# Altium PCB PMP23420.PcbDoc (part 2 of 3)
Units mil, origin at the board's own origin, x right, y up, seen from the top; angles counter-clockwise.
Board outline 5200 x 3400 mil, 6 copper layers (Top Layer, Midlayer 1, Midlayer 2, Midlayer 3, Midlayer 4, Bottom Layer), stack 61.536 mil thick; 227 components, 56 nets, 480 pads, 964 vias.
Unrouted connection lines stored in the file: 22.
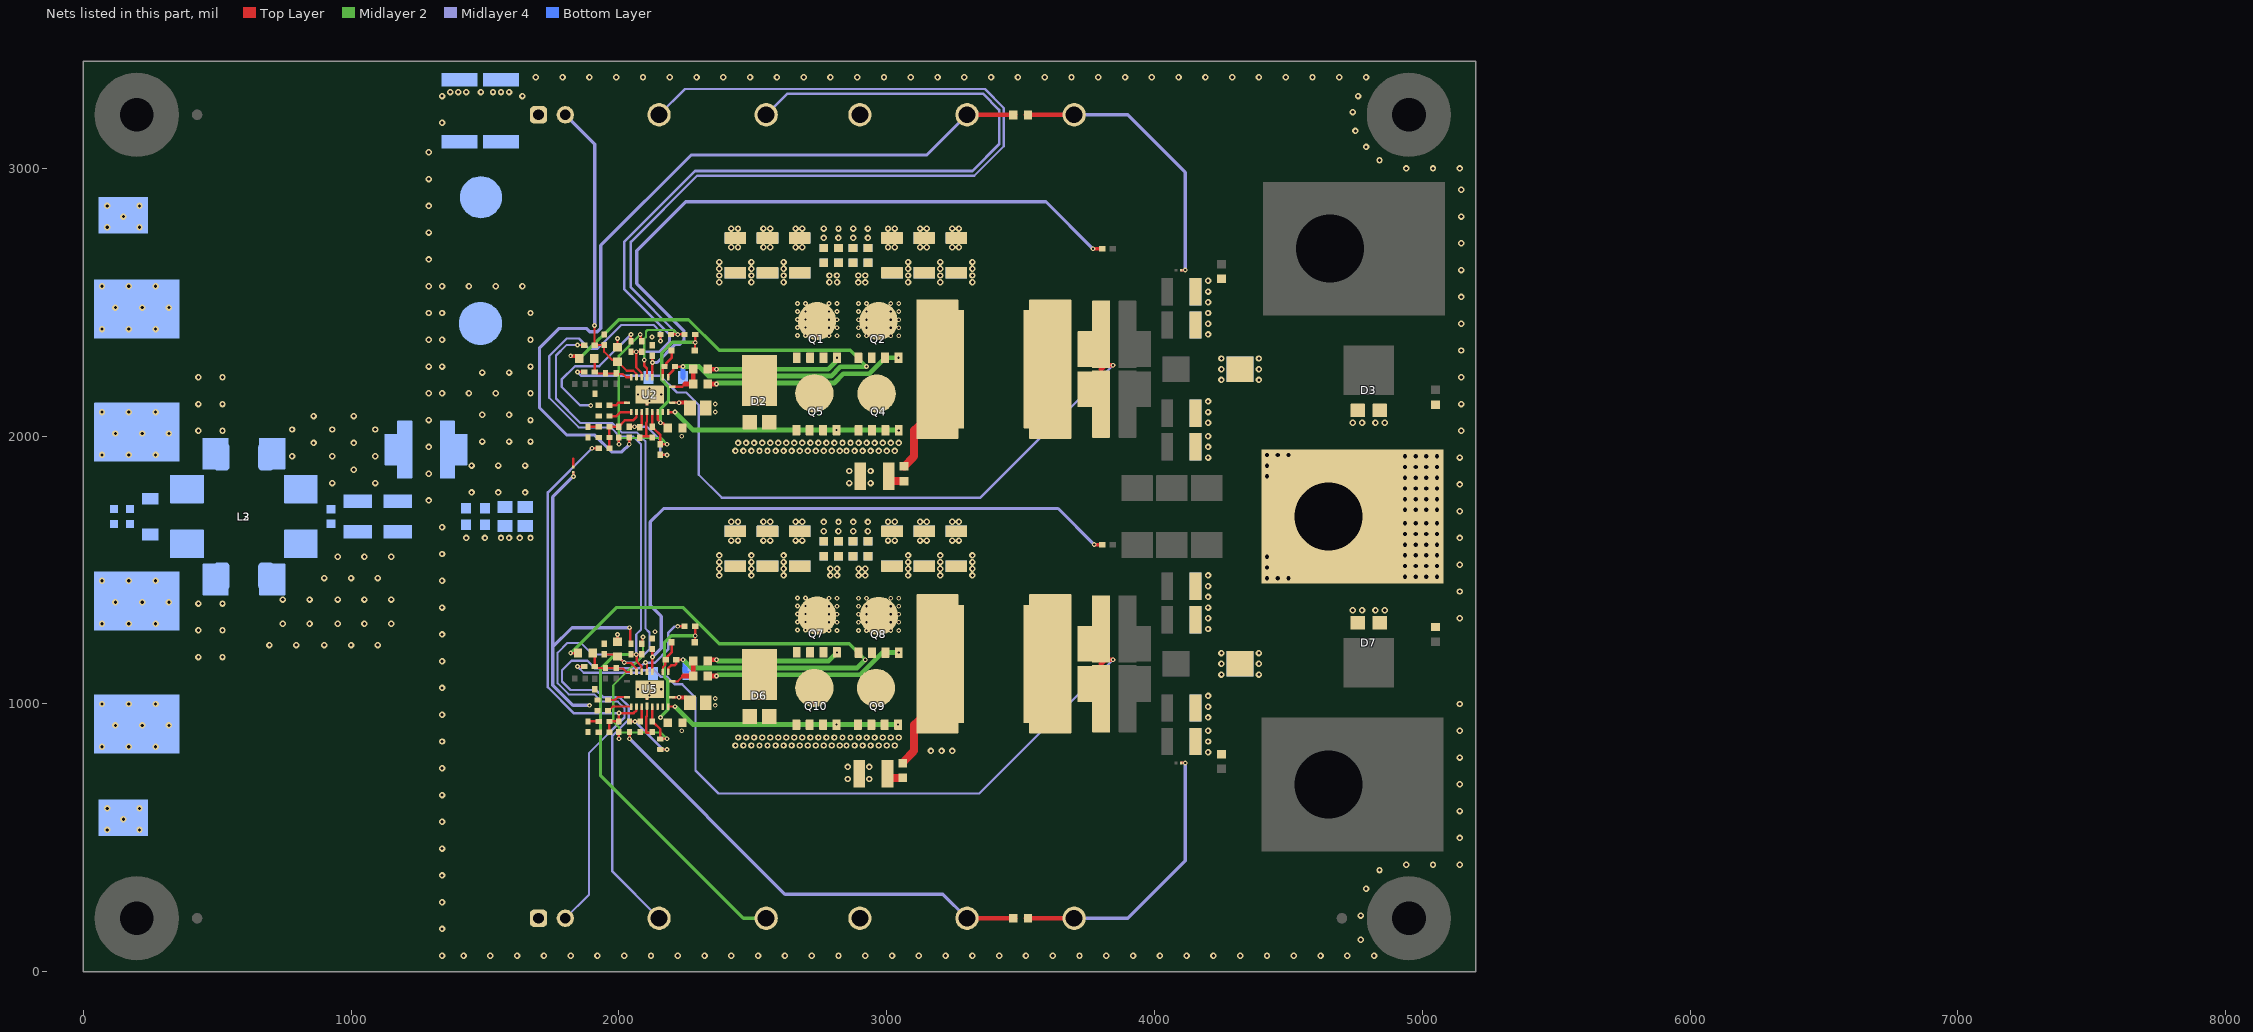
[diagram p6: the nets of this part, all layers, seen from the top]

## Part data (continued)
C51 C93: library part CMP-0006311-2, "CAP, CERM, 22 pF, 50 V, +/- 5%, C0G/NP0, AEC-Q200 Grade 1, 0402", Cap_Case=0402, Manufacturer=TDK, Supplier Part Number 1=445-12130-1-ND, TempCo=C0G/NP0, Tolerance_%=5%, Value1=Unknown, Value2=50V, ValueDisplayed=22pF
C52: library part CMP-0006353-2, "CAP, CERM, 0.022 uF, 25 V, +/- 10%, X7R, AEC-Q200 Grade 1, 0402", Cap_Case=0402, Manufacturer=MuRata, Supplier Part Number 1=490-6044-1-ND, TempCo=X7R, Tolerance_%=10%, Value1=Unknown, Value2=25V, ValueDisplayed=0.022uF
C53 C95: library part CMP-0006705-2, "CAP, CERM, 270 pF, 100 V, +/- 10%, X7R, 0402", Cap_Case=0402, Manufacturer=MuRata, Supplier Part Number 1=GRM155R72A271KA01D-ND, TempCo=X7R, Tolerance_%=10%, Value1=Unknown, Value2=100V, ValueDisplayed=270pF
C94: library part CMP-0006670-2, "CAP, CERM, 5600 pF, 25 V, +/- 10%, X7R, 0402", Cap_Case=0402, Manufacturer=MuRata, PartNumber=GRM155R71E562KA01D, Supplier Part Number 1=490-5420-1-ND, TempCo=X7R, Tolerance_%=10%, Value1=Unknown, Value2=25V, ValueDisplayed=5600pF
D1 D5: library part CMP-0076946-1, "Diode, Schottky, 100 V, 0.25 A, SOD-323F", Manufacturer=Nexperia, Supplier Part Number 1=568-6017-1-ND, Value1=0.25A, Value2=0.85V
D2 D6: library part CMP-0080010-1, "Diode, Schottky, 100 V, 5 A, AEC-Q101, PowerDI5", Manufacturer="Diodes Inc.", Supplier Part Number 1=PDS5100HQ-13DICT-ND, Value1=5A, Value2=0.71V
D3 D7: library part CMP-0048085-1, "Diode 40 V 10A Surface Mount TO-277A (SMPC)", Digikey Part Number=SS10P4HM3_A/HGICT-ND, Forward Current=10A, Manufacturer=Vishay, Max Surge Forward Current=280A, Mouser Part Number=78-SS10P4HM3_A/H, Operating Temperature Range="-55°C to +150°C", Peak Reverse Current=100uA, ValueDisplayed=750pF
D4 D8: library part Diode_Schottky, "Diode, Schottky, 100V, 2A, SOD-123", Alternate Manufacturer=-, Manufacturer=Nexperia
FID1 FID2 FID3 FID4 FID5 FID6: library part CMP-0077181-1, "Fiducial mark.  There is nothing to buy or mount.", Manufacturer=N/A
H1 H2 H3 H4: library part CMP-0003617-1, "Machine Screw, Round, #4-40 x 1/4, Nylon, Philips panhead", Manufacturer="B&F Fastener Supply", Supplier Part Number 1=H542-ND
H5 H6 H7 H8: library part CMP-0003610-1, "Standoff, Hex, 0.5\"L #4-40 Nylon", Manufacturer=Keystone, Supplier Part Number 1=36-1902C-ND
J1 J2 J7 J9 J10 J11: library part CMP-0055135-1, "Shorting Jumper, 5.375mm, 2 Position, Tin, SMT", Color=Silver, Manufacturer=Keystone, PartNumber=5102, Supplier Part Number 1=36-5102-ND
J3 J4: library part CMP-0079575-1, "Banana Jack Insul Nylon Red, TH", Color=Red, Current_A=15A, Manufacturer="Cinch Connectivity", PartNumber=108-0902-001, Supplier Part Number 1=J151-ND
J5 J6: library part CMP-0079574-1, "Banana Jack Insul Nylon Black, TH", Color=Black, Current_A=15A, Manufacturer="Cinch Connectivity", PartNumber=108-0903-001, Supplier Part Number 1=J152-ND
J8 J12: library part CMP-0075405-3, "Header, 100mil, 2x1, Gold, TH", Color=Black, Current_A=6.3A, Manufacturer=Samtec, PartNumber=TSW-102-07-G-S, Supplier Part Number 1=SAM1029-02-ND, Voltage_V=550V
L1: library part CMP-0048360-1, "1 µH Shielded Molded Inductor 22 A 2.9mOhm Max Nonstandard", Digikey Part Number=2457-XGL6060-102MEC-ND, Manufacturer=Coilcraft, Operating Temperature Range=to, Part Number=XGL6060-102MEC, Self Resonant Frequency=46MHz, Test Frequency=1MHz, Tolerance_%=20%
L2: library part CMP-0084691-1, "Coupled inductor,  ohm, AEC-Q200 Grade 1, SMD", Manufacturer=TDK, PartNumber=ACM12V-701-2PL-TL00
L3: library part CMP-0013197-2, "Coupled inductor, 2 uH,  A, 1.8 ohm, SMD", Manufacturer=MuRata, PartNumber=PLT10HH101150PNL, Supplier Part Number 1=490-12821-1-ND, ValueDisplayed=2uH
L4 L6: library part CMP-0041756-1, "Shielded Power Inductor 2.2uH 20% 28.5A 1.6mOhm DCRmax, AECQ200, 13.4x15.0x13.0mm SMT", Manufacturer=Coilcraft, Operating Temperature Range=to, Part Number=XGL1313-222MED, Self Resonant Frequency=25MHz, Test Frequency=1MHz, Tolerance_%=20%
L5 L7: library part CMP-0047844-1, "Power Choke Coil 2.5uH 20% 100kHz 2.53mOhm 32A AECQ200 13.3x12.8x8.0mm SMT", Manufacturer=CYNTEC, Operating Temperature Range="-55°C to +180°C", Test Frequency=100kHz, Tolerance_%=20%
LBL1: library part CMP-0003625-1, "Thermal Transfer Printable Labels, 0.650\" W x 0.200\" H - 10,000 per roll", Manufacturer=Brady, Supplier Part Number 1=97C5133
Logo1: library part CMP-0074844-1
Logo2: library part CMP-0074847-1, "FCC_disclaimer"
Logo3: library part CMP-0074769-1
NT1 NT2 NT3 NT4 NT5: library part CMP-0078142-3, "Single point connection between nets.", Manufacturer=N/A
Q1 Q2 Q7 Q8: library part CMP-0094035-1, "MOSFET N-Channel 80 V 13A (Ta), 59A (Tc) 3.7W (Ta), 73W (Tc) Surface Mount 5-DFN (5x6) (8-SOFL)", Digikey Part Number=488-NVMFS6H848NLT1GTR-ND, Drain To Source Breakdown Voltage=80V, Input Capacitace At Vds="1420pF @ 40V", Manufacturer=onsemi, Mouser Part Number=863-NVMFS6H848NLT1G, Operating Temperature Range="-55°C to +175°C", Power_W=3.7W, Pulse Drain Current=319A, Typ Forward Diode Voltage=0.81V
Q4 Q5 Q9 Q10: library part CMP-0032024-1, "N-Channel 80 V 24A (Ta), 160A (Tc) 3.8W (Ta), 167W (Tc) Surface Mount 5-DFN (5x6) (8-SOFL)", Digikey Part Number=488-NVMFS6H801NLT1GCT-ND, Drain To Source Breakdown Voltage=80V, Input Capacitace At Vds="5126pF @ 40V", Manufacturer=onsemi, Mouser Part Number=863-NVMFS6H801NLT1G, Operating Temperature Range="-55°C to +175°C", Power_W=3.8W, Pulse Drain Current=900A, Typ Forward Diode Voltage=0.76V
R1 R2: library part CMP-0015904-3, "RES, 1.0, 5%, 1 W, AEC-Q200 Grade 0, 2512", Manufacturer=Vishay-Dale, Power_W=1W, Supplier Part Number 1=541-1.0XCT-ND, TempCo="200 ppm/C", Tolerance_%=5%, Value_Code=1R00, ValueDisplayed=1.0
R3 R4 R54 R56: library part CMP-0023343-3, "RES, 0, 1%, 0.1 W, AEC-Q200 Grade 0, 0603", Manufacturer="Stackpole Electronics Inc", Power_W=100mW, Supplier Part Number 1=RMCF0603ZT0R00CT-ND, TempCo=ppm/C, Tolerance_%=1%, Value2=0.1W, Value_Code=0
R5 R30 R66 R67: library part CMP-0046355-1, "Res Current Sense Thick Film 1225 0.5m Ohm 5% 2W ±150ppm/°C Molded Emboss T/R", Digikey Part Number=RHM.0005BRCT-ND, Manufacturer="Rohm Semiconductor", Mouser Part Number=755-PML100HZPJV0L5, Operating Temperature Range="-55°C to +155°C", Part Number=PML100HZPJV0L5, Power_W=2W, TempCo=150ppm/°C, Tolerance_%=5%
R6: library part CMP-0022060-4, "RES, 150 k, 1%, 0.1 W, AEC-Q200 Grade 0, 0603", Manufacturer=Vishay-Dale, Power_W=100mW, Supplier Part Number 1=541-150KHCT-ND, TempCo="100 ppm/C", Tolerance_%=1%, Value2=0.1W, Value_Code=150k
R7 R15 R31 R32 R43 R49: library part CMP-0081856-1, "RES, 0, 0%, 0.2 W, AEC-Q200 Grade 0, 0402", Manufacturer=Vishay-Dale, Power_W=200mW, Supplier Part Number 1=541-0.0YBTR-ND, Tolerance_%=0%, Value2=0.2W, Value_Code=0
R8 R33: library part CMP-0001672-1, "1.2 mOhms ±1% 5W Chip Resistor 2512 (6432 Metric) Automotive AEC-Q200, Current Sense, Non-Inductive Metal Element", Digikey Part Number=804-Y14830R00120F9RCT-ND, Manufacturer="Vishay Foil Resistors", Operating Temperature Range="-65°C to +170°C", Power_W=5W, Tolerance_%=1%
R9: library part CMP-0026517-2, "RES, 6.81 k, 1%, 0.063 W, AEC-Q200 Grade 0, 0402", Manufacturer=Vishay-Dale, Power_W=63mW, Supplier Part Number 1=541-6.81KLCT-ND, TempCo="100 ppm/C", Tolerance_%=1%, Value2=0.063W, Value_Code=6k81, ValueDisplayed=6.81k
R10 R19 R46 R50: library part CMP-0026753-1, "RES, 100 k, 1%, 0.063 W, AEC-Q200 Grade 0, 0402", Manufacturer="Stackpole Electronics Inc", PartNumber=RMCF0402FT100K, Power_W=63mW, Supplier Part Number 1=RMCF0402FT100KCT-ND, TempCo="100 ppm/C", Tolerance_%=1%, Value2=0.063W, Value_Code=100k
R11 R36: library part Resistor, "RES, xxx ohm, x%, xW, [PackageReference]", Alternate Manufacturer=-, Manufacturer="Used in BOM report"
R12 R37: library part CMP-0026404-2, "RES, 49.9, 1%, 0.063 W, AEC-Q200 Grade 0, 0402", Manufacturer=Vishay-Dale, Power_W=63mW, Supplier Part Number 1=541-49.9LCT-ND, TempCo="100 ppm/C", Tolerance_%=1%, Value2=0.063W, Value_Code=49R9, ValueDisplayed=49.9
R13 R38 R51: library part CMP-0086542-2, "RMCF/RMCP Series General Purpose Thick Film Standard Power and High Power Chip Resistor", Manufacturer=Stackpole, TempCo=-, Value1=0
R14 R39: library part Resistor, "RES, 1.0 ohm, 5%, 0.5W, 1210", Alternate Manufacturer=-, Manufacturer=Stackpole, PartNumber=RMCF1210JT4R70
R16 R41: library part Resistor, "RES, xxx ohm, x%, xW, [PackageReference]", Alternate Manufacturer=-
R17: library part CMP-0022448-4, "RES, 49.9, 1%, 0.1 W, AEC-Q200 Grade 0, 0603", Manufacturer=Vishay-Dale, Power_W=100mW, Supplier Part Number 1=541-49.9HCT-ND, TempCo="100 ppm/C", Tolerance_%=1%, Value2=0.1W, Value_Code=49R9, ValueDisplayed=49.9
R18 R44: library part CMP-0026013-3, "RES, 147 k, 1%, 0.063 W, AEC-Q200 Grade 0, 0402", Manufacturer=Vishay-Dale, Power_W=63mW, Supplier Part Number 1=541-147KLCT-ND, TempCo="100 ppm/C", Tolerance_%=1%, Value2=0.063W, Value_Code=147k
R20 R40 R45: library part CMP-0081856-1, "RES, 0, 0%, 0.2 W, AEC-Q200 Grade 0, 0402", Manufacturer=Vishay-Dale, PartNumber=CRCW04020000Z0EDHP, Power_W=200mW, Supplier Part Number 1=541-0.0YBTR-ND, Tolerance_%=0%, Value2=0.2W, Value_Code=0
R22: library part CMP-0026399-2, "RES, 48.7 k, 1%, 0.063 W, AEC-Q200 Grade 0, 0402", Manufacturer=Vishay-Dale, PartNumber=CRCW040248K7FKED, Power_W=63mW, Supplier Part Number 1=541-48.7KLCT-ND, TempCo="100 ppm/C", Tolerance_%=1%, Value2=0.063W, Value_Code=48k7, ValueDisplayed=48.7k
R23 R35: library part CMP-0026753-1, "RES, 100 k, 1%, 0.063 W, AEC-Q200 Grade 0, 0402", Manufacturer="Stackpole Electronics Inc", Power_W=63mW, Supplier Part Number 1=RMCF0402FT100KCT-ND, TempCo="100 ppm/C", Tolerance_%=1%, Value2=0.063W, Value_Code=100k
R24: library part CMP-0026329-2, "RES, 3.01 k, 1%, 0.063 W, AEC-Q200 Grade 0, 0402", Manufacturer=Vishay-Dale, Power_W=63mW, Supplier Part Number 1=541-3.01KLCT-ND, TempCo="100 ppm/C", Tolerance_%=1%, Value2=0.063W, Value_Code=3k01, ValueDisplayed=3.01k
R25: library part CMP-0026449-2, "RES, 54.9 k, 1%, 0.063 W, AEC-Q200 Grade 0, 0402", Manufacturer=Vishay-Dale, Power_W=63mW, Supplier Part Number 1=541-54.9KLCT-ND, TempCo="100 ppm/C", Tolerance_%=1%, Value2=0.063W, Value_Code=54k9, ValueDisplayed=54.9k
R26: library part CMP-0026067-3, "RES, 19.1 k, 1%, 0.063 W, AEC-Q200 Grade 0, 0402", Manufacturer=Vishay-Dale, Power_W=63mW, Supplier Part Number 1=541-19.1KLCT-ND, TempCo="100 ppm/C", Tolerance_%=1%, Value2=0.063W, Value_Code=19k1, ValueDisplayed=19.1k
R29: library part CMP-0021990-4, "RES, 100 k, 1%, 0.1 W, AEC-Q200 Grade 0, 0603", Manufacturer=Vishay-Dale, PartNumber=CRCW0603100KFKEA, Power_W=100mW, Supplier Part Number 1=541-100KHCT-ND, TempCo="100 ppm/C", Tolerance_%=1%, Value2=0.1W, Value_Code=100k
R34: library part CMP-0026412-2, "RES, 4.75 k, 1%, 0.063 W, AEC-Q200 Grade 0, 0402", Manufacturer=Vishay-Dale, PartNumber=CRCW04024K75FKED, Power_W=63mW, Supplier Part Number 1=541-4.75KLCT-ND, TempCo="100 ppm/C", Tolerance_%=1%, Value2=0.063W, Value_Code=4k75, ValueDisplayed=4.75k
R42: library part CMP-0022448-4, "RES, 49.9, 1%, 0.1 W, AEC-Q200 Grade 0, 0603", Manufacturer=Vishay-Dale, PartNumber=CRCW060349R9FKEA, Power_W=100mW, Supplier Part Number 1=541-49.9HCT-ND, TempCo="100 ppm/C", Tolerance_%=1%, Value2=0.1W, Value_Code=49R9, ValueDisplayed=49.9
R48: library part CMP-0026555-2, "RES, 7.50 k, 1%, 0.063 W, AEC-Q200 Grade 0, 0402", Manufacturer=Vishay-Dale, PartNumber=CRCW04027K50FKED, Power_W=63mW, Supplier Part Number 1=541-7.50KLCT-ND, TempCo="100 ppm/C", Tolerance_%=1%, Value2=0.063W, Value_Code=7k50, ValueDisplayed=7.50k
R52: library part CMP-0026605-2, "RES, 90.9 k, 1%, 0.063 W, AEC-Q200 Grade 0, 0402", Manufacturer=Vishay-Dale, Power_W=63mW, Supplier Part Number 1=541-90.9KLCT-ND, TempCo="100 ppm/C", Tolerance_%=1%, Value2=0.063W, Value_Code=90k9, ValueDisplayed=90.9k
R53: library part CMP-0026067-3, "RES, 19.1 k, 1%, 0.063 W, AEC-Q200 Grade 0, 0402", Manufacturer=Vishay-Dale, PartNumber=CRCW040219K1FKED, Power_W=63mW, Supplier Part Number 1=541-19.1KLCT-ND, TempCo="100 ppm/C", Tolerance_%=1%, Value2=0.063W, Value_Code=19k1, ValueDisplayed=19.1k
R64 R65: library part CMP-0001672-1, "1.2 mOhms ±1% 5W Chip Resistor 2512 (6432 Metric) Automotive AEC-Q200, Current Sense, Non-Inductive Metal Element", Digikey Part Number=804-Y14830R00120F9RCT-ND, Manufacturer="Vishay Foil Resistors", Operating Temperature Range="-65°C to +170°C", Part Number=Y14830R00120F9R, Power_W=5W, Tolerance_%=1%
SH-J1 SH-J2: library part CMP-0003761-2, "Shunt, 2.54mm, Gold, Black", Manufacturer="Wurth Elektronik", Supplier Part Number 1=732-2678-ND
T1 T2 T3: library part CMP-0055443-2, "Terminal 90A Lug", Manufacturer=Panduit, PartNumber=CB70-14-CY, Supplier Part Number 1=CB70-14-CY-ND, Voltage_V=600V
TP1 TP2: library part CMP-0055153-2, "Test Point, Compact, SMT", Manufacturer="Keystone Electronics", PartNumber=5016, Supplier Part Number 1=36-5016TR-ND
TP3 TP9: library part CMP-0055147-1, "Test Point, Multipurpose, Red, TH", Color=Red, Manufacturer=Keystone, PartNumber=5010, Supplier Part Number 1=36-5010-ND
TP4 TP5 TP6 TP10 TP11 TP12: library part CMP-0055149-1, "Test Point, Multipurpose, White, TH", Color=White, Manufacturer=Keystone, PartNumber=5012, Supplier Part Number 1=36-5012-ND
TP7 TP8: library part CMP-0055148-1, "Test Point, Multipurpose, Black, TH", Color=Black, Manufacturer=Keystone, PartNumber=5011, Supplier Part Number 1=36-5011-ND
U2 U5: library part CMP-0032794-1, "80-V, Automotive, Synchronous, Buck DC/DC Controller with Ultra-Low IQ and Dual Random Spread Spectrum", Manufacturer="Texas Instruments", Max Supply Voltage=80V, Min Supply Voltage=3.5V, Nominal Supply Current=9.5-124uA, Operating Temperature Range="-40°C to +150°C", Output Voltage=3/5/12/0.8-55V, Switching Frequency=100-2200kHz

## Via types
v1: diameter 24, hole 12, Top Layer to Bottom Layer, tented both sides, 565 vias
v2: diameter 32, hole 16, Top Layer to Bottom Layer, 174 vias
v3: diameter 18, hole 8, Top Layer to Bottom Layer, tented bottom, 88 vias
v4: diameter 18, hole 8, Top Layer to Bottom Layer, tented both sides, 71 vias
v5: diameter 24, hole 12, Top Layer to Bottom Layer, tented top, 58 vias
v6: diameter 19.68, hole 7.87, Top Layer to Bottom Layer, tented both sides, 8 vias

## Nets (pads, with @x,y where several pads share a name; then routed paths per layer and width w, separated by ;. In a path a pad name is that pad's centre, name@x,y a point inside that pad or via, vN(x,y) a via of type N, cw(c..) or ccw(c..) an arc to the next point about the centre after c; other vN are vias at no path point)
+Filter: C5.2 C6.2 C7.1 J1.2 J2.1 L1.2 L2.3 L3.3
  other v1: 930,1825 1090,1825 1010,1875 780,1925 930,1925 1090,1925 860,1975 1010,1975 780,2025 930,2025 1090,2025 860,2075 1010,2075
+Vin_Main: C2.1 C3.1 C4.1 J2.2 J3.1 J4.1 L2.2 L3.4 TP1.1
  other v5: 70,1930 170,1930 270,1930 120,2010 220,2010 320,2010 430,2020 520,2020 70,2090 170,2090 270,2090 430,2120 520,2120 430,2220 520,2220 70,2400 170,2400 270,2400 120,2480 220,2480 320,2480 70,2560 170,2560 270,2560 90,2780 210,2780 150,2820 90,2860 210,2860
AGND1: C33.1 C51.2 C52.2 NT2.2 NT3.1 R18.2 R20.2 R25.1 R26.1 U2.5 | length 686.8
  Top Layer w9: NT3.1@1830,1885 1830,1915.76 ; R20.2@2045,2354.69 v4(2045,2380) ; R26.1@2080,1995.32 2084.96,2000.27 2102.22,2000.27 ; 2102.22,2051.05 2102.22,2000.27 ; 2104.18,2053.02 2105.16,2053.99 U2.5@2105.16,2090.04 ; C33.1@2125,1995.32 2120.04,2000.27 2102.22,2000.27
  Midlayer 4 w9: v4(1895.16,2114.84) 1855.75,2114.84 1786.25,2184.34 1786.25,2211.48 1836.15,2261.37 1926.37,2261.37 v4(2045,2380)
AGND2: C75.1 C93.2 C94.2 NT3.2 NT5.2 R44.2 R45.2 R52.1 R53.1 U5.5 | length 1496.5
  Top Layer w9: v4(2040,1285) 2041.72,1283.28 2041.72,1227.96 R45.2@2045,1224.69 ; U5.5@2105.16,990.04 2105.16,955.73 2102.22,952.79 2102.22,892.26 2120.22,892.26 C75.1@2124.69,896.73
  Top Layer w10: v4(1830,1850) NT3.2@1830,1865
  Midlayer 4 w12: v4(1830,1850) 1753.37,1773.37 1753.37,1213.37 ; v4(1890,995) 1828.33,995 1753.37,1069.96 1753.37,1213.37 ; v4(2040,1285) 1825,1285 1753.37,1213.37
Bode1: R17.1 R23.2 TP6.1 | length 2993.2
  Top Layer w9: v4(2039,1970) R23.2@2039,1995.31
  Top Layer w16: TP6.1@3300,3200 R17.1@3480.31,3200
  Midlayer 4 w12: v4@2040,1970 2011.22,1941.22 1972.56,1941.22 1909.57,2004.21 1806.24,2004.21 1703.46,2106.99 1703.46,2328.46 1777.61,2402.61 1878.37,2402.61 1890.98,2390 1919.04,2390 1932.44,2403.4 1932.44,2712.44 2270,3050 3150,3050 TP6.1@3300,3200
Bode2: R42.1 R50.2 TP12.1 | length 1743.2
  Top Layer w9: v4(2040,870) R50.2@2040,895.31
  Top Layer w16: TP12.1@3300,200 R42.1@3480.31,200
  Midlayer 4 w12: v4(2040,870) 2620,290 3210,290 TP12.1@3300,200
CNFG1: R25.2 U2.1 | length 70
  Top Layer w9: R25.2@1964.69,2115 1988.69,2115 1999.16,2125.47 U2.1@2030.35,2125.47
CNFG2: R52.2 U5.1 | length 75
  Top Layer w8: R52.2@1959.69,1015 1985,1015 1995.47,1025.47 U5.1@2030.35,1025.47
COMP1: C51.1 R19.1 R24.2 R49.2 U2.3 | length 216.3
  Top Layer w9: R49.2@1964.69,1955 C51.1@1964.68,1995 R24.2@1964.69,2035 1964.84,2034.84 1999.84,2034.84 R19.1@2000,2034.68 2000,2036.65 2022.22,2058.87 2053.3,2058.87 2065.79,2071.36 U2.3@2065.79,2090.04
COMP2: C93.1 R46.2 R48.2 R49.1 U5.3 | length 1482.6
  Top Layer w9: v4(1900,1955) R49.1@1925.32,1955 ; C93.1@1964.68,895 R48.2@1964.69,935 1964.84,934.84 1999.84,934.84 R46.2@2000,934.69 v4(2000,966.04) 2000.18,965.85 2055,965.85 2065.37,976.22 2065.37,989.62 U5.3@2065.79,990.04
  Midlayer 4 w9: v4(1900,1955) 1735,1790 1735,1062.35 1832.35,965 1998.96,965 v4(2000,966.04)
EN1: J8.2 R6.1 R9.2 R32.2 U2.18 | length 1133.4
  Top Layer w8: v4(1909.57,2412.87) 1909.63,2412.81 1909.63,2342.19 R32.2@1911.65,2340.16 ; R32.2@1909.69,2340 1911.5,2340 R32.2@1911.65,2340.16 ; U2.18@2065.79,2219.96 2064.87,2220.88 2064.87,2233.57 2054.15,2244.28 2029.14,2244.28 1995.98,2277.44 R6.1@1995,2277.44 1987.13,2285.31 1974.33,2285.31 1945,2314.65 1945,2338.35 1943.19,2340.16 R32.2@1911.65,2340.16
  Midlayer 4 w12: J8.2@1800,3200 1909.57,3090.43 v4(1909.57,2412.87)
EN2: J12.2 R29.1 R32.1 R34.2 U5.18 | length 3306.8
  Top Layer w8: v4(1845,2340) R32.1@1870.32,2340 ; R34.2@1945,1185.31 1987.13,1185.31 R29.1@1995,1177.44 1995.98,1177.44 2018.43,1155 v4(2020,1155) 2021.91,1153.09 2045.35,1153.09 2064.87,1133.57 2064.87,1120.88 U5.18@2065.79,1119.96
  Midlayer 4 w8: J12.2@1800,200 1888.78,288.78 1888.78,817.56 2020.87,949.65 2020.87,983.65 1995.69,1008.83 1935.18,1008.83 1908.14,1035.87 1812.74,1035.87 1771.25,1077.36 1771.25,1191.25 1808.37,1228.37 1857.3,1228.37 1900.36,1185.31 1989.69,1185.31 v4(2020,1155) 2064.52,1155 2114.13,1204.61 2114.13,1267.22 2099.05,1282.29 2099.05,1981.29 2066.22,2014.13 2010.87,2014.13 1976.22,2048.78 1856.89,2048.78 1765,2140.67 1765,2301.1 1803.9,2340 v4(1845,2340)
FB1: R22.2 R23.1 R26.2 U2.4 | length 315.1
  Top Layer w9: R23.1@2040,2034.68 2040.16,2034.84 2057.84,2034.84 v4(2058,2035) 2058.66,2034.34 2079.66,2034.34 2080,2034.69 2085.34,2040.03 2085.34,2064.6 2085.47,2064.73 U2.4@2085.47,2090.04 ; R22.2@2155,1930.31 2155.16,1930.16 2179.84,1930.16 v4(2180,1930)
  Midlayer 4 w9: v4(2058,2035) 2105,2035 2155,1985 2155,1940 2163.28,1931.72 2178.28,1931.72 v4(2180,1930)
FB2: R50.1 R51.2 R53.2 U5.4 | length 284
  Top Layer w9: R50.1@2040,934.68 2060,934.69 R53.2@2080,934.69 ; R53.2@2085.34,934.69 2085.34,955.78 2085.47,955.91 U5.4@2085.47,990.04 ; R51.2@2155,830.32 2155.16,830.16 2179.84,830.16 v4(2180,830)
  Midlayer 4 w9: v4(2060,935) 2165,830 v4(2180,830)
GND: C5.1 C6.1 C7.2 C8.2 C9.2 C10.2 C11.2 C12.1 C13.1 C14.1 C15.1 C16.1 C17.2 C18.2 C19.2 C20.2 C21.1 C22.1 C23.1 C24.1 C25.2 C26.2 C27.2 C28.2 C29.1 C30.2 C34.2 C36.2 C37.2 C38.2 C39.2 C40.2 C41.2 C42.2 C43.2 C44.2 C45.2 C46.2 C47.2 C48.1 C53.1 C54.1 C55.1 C56.1 C57.1 C58.1 C59.2 C60.2 C61.2 C62.2 C63.1 C64.1 C65.1 C66.1 C67.1 C68.2 C69.2 C70.2 C71.2 C72.2 C76.2 C78.2 C79.2 C80.2 C81.2 C82.2 C83.2 C84.2 C85.2 C86.2 C87.2 C88.2 C89.2 C90.1 C95.1 C100.1 C101.1 C102.1 C103.1 D2.1 D2.2 D3.1 D3.2 D4.2 D6.1 D6.2 D7.1 D7.2 D8.2 J7.1 J8.1 J12.1 L2.4 L3.2 NT2.1 NT5.1 Q4.1 Q4.2 Q4.3 Q5.1 Q5.2 Q5.3 Q9.1 Q9.2 Q9.3 Q10.1 Q10.2 Q10.3 R1.1 R2.1 R9.1 R14.1 R34.1 R39.1 T2.1 TP7.1 TP8.1 U2.8 U2.21 U5.8 U5.21 | length 103.3
  Top Layer w10: v6(2071.69,1055) 2076.54,1055 2105,1026.54 NT5.1@2105,1020 ; v6(2071.69,2155) 2076.54,2155 2105,2126.54 NT2.1@2105,2120
  other v1: 1340,60 1420,60 1520,60 1620,60 1720,60 1820,60 1920,60 2020,60 2120,60 2220,60 2320,60 2420,60 2520,60 2620,60 2720,60 2820,60 2920,60 3020,60 3120,60 3220,60 3320,60 3420,60 3520,60 3620,60 3720,60 3820,60 3920,60 4020,60 4120,60 4220,60 4320,60 4420,60 4520,60 4620,60 4720,60 4820,60 4770,120 1340,160 4770,210 1340,260 4790,310 1340,360 4840,380 4940,400 5040,400 5140,400 1340,460 5140,500 1340,560 5140,600 1340,660 5140,700 2855,720 2935,720 1340,760 2855,765 2935,765 5140,800 4200,820 3165,825 3205,825 3245,825 2435,845 2465,845 2495,845 2525,845 2555,845 2585,845 2615,845 2645,845 2675,845 2705,845 2735,845 2765,845 2795,845 2825,845 2850,845 2880,845 2910,845 2940,845 2970,845 3000,845 3030,845 1340,860 4200,860 2445,875 2475,875 2505,875 2535,875 2565,875 2595,875 2625,875 2655,875 2685,875 2715,875 2745,875 2775,875 2805,875 2835,875 2865,875 2895,875 2925,875 2955,875 2985,875 3015,875 3045,875 4200,900 5140,900 4200,950 1340,960 4200,990 5140,1000 4200,1030 1340,1060 4250,1110 4390,1110 4250,1150 4390,1150 1340,1160 4250,1190 4390,1190 695,1220 795,1220 900,1220 1000,1220 1100,1220 1340,1260 4200,1280 745,1300 845,1300 950,1300 1050,1300 1150,1300 4200,1320 5140,1320 4740,1350 4775,1350 4825,1350 4860,1350 1340,1360 4200,1360 745,1390 845,1390 950,1390 1050,1390 1150,1390 4200,1400 5140,1420 4200,1440 1340,1460 900,1470 1000,1470 1100,1470 4200,1480 5140,1520 950,1550 1050,1550 1150,1550 1340,1560 2419.87,1610.18 2444.87,1610.18 2539.87,1610.18 2564.87,1610.18 2659.87,1610.22 2684.87,1610.22 3004.87,1610.22 3029.87,1610.22 3124.87,1610.22 3149.87,1610.22 3244.87,1610.18 3269.87,1610.18 1430,1620 1500,1620 1560,1620 1590,1620 1630,1620 1670,1620 5140,1620 2764.87,1645.18 2819.87,1645.18 2874.87,1645.18 2929.87,1645.18 1340,1660 2419.87,1680.18 2444.87,1680.18 2539.87,1680.18 2564.87,1680.18 2659.87,1680.22 2684.87,1680.22 2765,1680 2820,1680 2875,1680 2930,1680 3004.87,1680.22 3029.87,1680.22 3124.87,1680.22 3149.87,1680.22 3244.87,1680.18 3269.87,1680.18 5140,1720 1290,1760 5140,1820 2860,1825 2940,1825 1290,1860 2860,1870 2940,1870 4200,1920 5140,1920 2435,1945 2465,1945 2495,1945 2525,1945 2555,1945 2585,1945 2615,1945 2645,1945 2675,1945 2705,1945 2735,1945 2765,1945 2795,1945 2825,1945 2850,1945 2880,1945 2910,1945 2940,1945 2970,1945 3000,1945 3030,1945 1290,1960 4200,1960 2445,1975 2475,1975 2505,1975 2535,1975 2565,1975 2595,1975 2625,1975 2655,1975 2685,1975 2715,1975 2745,1975 2775,1975 2805,1975 2835,1975 2865,1975 2895,1975 2925,1975 2955,1975 2985,1975 3015,1975 3045,1975 4200,2000 5145,2020 4200,2050 4740,2050 4775,2050 4825,2050 4860,2050 1290,2060 4200,2090 5145,2120 4200,2130 1290,2160 4250,2210 4390,2210 5145,2220 4250,2250 4390,2250 1290,2260 4250,2290 4390,2290 5145,2320 1290,2360 4200,2380 4200,2420 5145,2420 1290,2460 4200,2460 4200,2500 5145,2520 4200,2540 1290,2560 4200,2580 5145,2620 1290,2660 2419.87,2705.18 2444.87,2705.18 2539.87,2705.18 2564.87,2705.18 2659.87,2705.22 2684.87,2705.22 3004.87,2705.22 3029.87,2705.22 3124.87,2705.22 3149.87,2705.22 3244.87,2705.18 3269.87,2705.18 5145,2720 2764.87,2740.18 2819.87,2740.18 2874.87,2740.18 2929.87,2740.18 1290,2760 2419.87,2775.18 2444.87,2775.18 2539.87,2775.18 2564.87,2775.18 2659.87,2775.22 2684.87,2775.22 2765,2775 2820,2775 2875,2775 2930,2775 3004.87,2775.22 3029.87,2775.22 3124.87,2775.22 3149.87,2775.22 3244.87,2775.18 3269.87,2775.18 5145,2820 1290,2860 5145,2920 1290,2960 4940,3000 5040,3000 5140,3000 4840,3030 1290,3060 4790,3080 4750,3140 1340,3170 4740,3210 1340,3270 1640,3270 4760,3270 1370,3285 1400,3285 1430,3285 1485,3285 1530,3285 1560,3285 1590,3285 1690,3340 1790,3340 1890,3340 1990,3340 2090,3340 2190,3340 2290,3340 2390,3340 2490,3340 2590,3340 2690,3340 2790,3340 2890,3340 2990,3340 3090,3340 3190,3340 3290,3340 3390,3340 3490,3340 3590,3340 3690,3340 3790,3340 3890,3340 3990,3340 4090,3340 4190,3340 4290,3340 4390,3340 4490,3340 4590,3340 4690,3340 4790,3340
  other v2: 4420,1470 4460,1470 4500,1470 4935,1475 4975,1475 5015,1475 5055,1475 4420,1510 4935,1515 4975,1515 5015,1515 5055,1515 4420,1550 4935,1555 4975,1555 5015,1555 5055,1555 4935,1595 4975,1595 5015,1595 5055,1595 4935,1635 4975,1635 5015,1635 5055,1635 4935,1675 4975,1675 5015,1675 5055,1675 4935,1725 4975,1725 5015,1725 5055,1725 4935,1765 4975,1765 5015,1765 5055,1765 4935,1805 4975,1805 5015,1805 5055,1805 4935,1845 4975,1845 5015,1845 5055,1845 4420,1850 4935,1885 4975,1885 5015,1885 5055,1885 4420,1890 4935,1925 4975,1925 5015,1925 5055,1925 4420,1930 4460,1930 4500,1930
  other v4: 2235,900 2360,995 2360,1020 2135,1270 2235,2000 2360,2090 2360,2120 2124,2370
  other v6: 2115,1031.38 2158.31,1055 2115,1078.62 2115,2131.38 2158.31,2155 2115,2178.62
GNDin: C2.2 C3.2 C4.2 J5.1 J6.1 J7.2 L2.1 L3.1 TP2.1
  other v5: 90,530 210,530 150,570 90,610 210,610 70,840 170,840 270,840 120,920 220,920 320,920 70,1000 170,1000 270,1000 430,1175 520,1175 430,1275 520,1275 70,1300 170,1300 270,1300 430,1375 520,1375 120,1380 220,1380 320,1380 70,1460 170,1460 270,1460
HO1: R4.1 R54.1 U2.11 | length 143.8
  Top Layer w9: U2.11@2199.65,2184.53 2236.46,2184.53 2246.93,2195
  Top Layer w18: 2246.93,2195 R54.1@2275,2195 ; R4.1@2274.33,2256.98 2273.35,2256 2277.44,2251.91 R4.1@2277.44,2250 R54.1@2277.44,2195
HO2: R3.1 R56.1 U5.11 | length 141.3
  Top Layer w8: U5.11@2199.65,1084.53 2219.97,1084.53 2240.44,1105
  Top Layer w18: 2240.44,1105 R56.1@2277.44,1105 R3.1@2277.44,1160
ISNS+1: C49.2 R11.1 R12.1 R16.2 U2.19 | length 199.8
  Top Layer w8: R12.1@1907.56,2245 R12.1@1909.68,2242.87 ; R11.1@1907.56,2290 1909.68,2287.87 R12.1@1909.68,2242.87 ; R12.1@1909.68,2240 R12.1@1909.68,2242.87 ; U2.19@2046.1,2219.96 2027.45,2219.96 2015,2232.41 1992.27,2232.41 C49.2@1990,2234.69 R16.2@1950,2234.69 1917.87,2234.69 R12.1@1909.68,2242.87
ISNS+2: C91.2 R36.1 R37.1 R41.2 U5.19 | length 187.3
  Top Layer w8: R36.1@1902.56,1190 1909.68,1182.87 R37.1@1909.68,1140 ; R37.1@1917.87,1134.69 R41.2@1950,1134.69 C91.2@1990,1134.69 1992.27,1132.41 2015,1132.41 2027.45,1119.96 U5.19@2046.1,1119.96
LO1: Q4.4 Q5.4 U2.9 | length 889.3
  Top Layer w9: U2.9@2183.9,2090.04 v4(2210,2090)
  Midlayer 2 w18: v4(2210,2090) 2277.1,2022.9 v3(2812.54,2022.9) 3043.93,2022.9 v3(3045,2021.83)
LO2: Q9.4 Q10.4 U5.9 | length 886.4
  Top Layer w8: U5.9@2183.9,990.04 U5.9@2183.9,990.04 v4(2210,990)
  Midlayer 2 w18: v4(2210,990) 2277.1,922.9 v3(2812.54,922.9) v3(3042.54,922.9)
NetC1_1: C1.1 R1.2 R2.2
NetC35_2: C35.2 R14.2 | length 54.3
  Top Layer w30: R14.2@3010.71,1832.44 C35.2@3065,1832.44
NetC52_1: C52.1 R24.1 | length 40.4
  Top Layer w9: C52.1@1885,2034.68 1885.16,2034.84 1925.16,2034.84 R24.1@1925.32,2035
NetC77_2: C77.2 R39.2 | length 50.2
  Top Layer w30: R39.2@3009.8,724.25 C77.2@3060.01,724.25
NetC94_1: C94.1 R48.1 | length 40.4
  Top Layer w9: C94.1@1885,934.68 1885.16,934.84 1925.16,934.84 R48.1@1925.32,935
NetL4_2: L4.2 L5.2 R5.1 R8.1 R12.2 R64.1 R66.1 | length 2627.6
  Top Layer w9: v4(1845,2240) R12.2@1868.35,2240
  Top Layer w12: R12.2@1868.35,2240 R12.2@1870.31,2240
  Top Layer w18: 3800.79,2250 3815.79,2265 v4(3845,2265)
  Midlayer 4 w9: v4(1845,2240) 1859.13,2225.87 2154.36,2225.87 2216.98,2163.25 2251.37,2163.25 2298.46,2116.17 2298.46,1855.83 2383.86,1770.43 3350.43,1770.43 v4(3845,2265)
NetL6_2: L6.2 L7.2 R30.1 R33.1 R37.2 R65.1 R67.1 | length 2645.7
  Top Layer w9: v4(1845,1140) R37.2@1870.31,1140
  Top Layer w18: 3800.79,1150 3815.79,1165 v4(3845,1165)
  Midlayer 4 w9: v4(1845,1140) 1845.65,1140 1868.89,1116.75 2083.18,1116.75 2092.29,1125.87 2133.12,1125.87 2157.77,1101.22 2180.19,1101.22 2207.92,1073.49 2236.03,1073.49 2286.28,1023.24 2286.28,751.42 2371.86,665.85 3345.85,665.85 v4(3845,1165)
NetNT1_1: NT1.1 R17.2 TP3.1 | length 1064.4
  Top Layer w9: NT1.1@4100,2620 v4(4115,2620)
  Top Layer w16: R17.2@3519.69,3200 R17.2@3527.56,3200 TP3.1@3700,3200
  Midlayer 4 w12: TP3.1@3700,3200 3900,3200 4115,2985 v4(4115,2620)
NetNT4_1: NT4.1 R42.2 TP9.1 | length 1064.4
  Top Layer w9: NT4.1@4100,780 v4(4115,780)
  Top Layer w16: R42.2@3519.69,200 R42.2@3527.56,200 TP9.1@3700,200
  Midlayer 4 w12: TP9.1@3700,200 3900,200 4115,415 v4(4115,780)
NetQ1_4: Q1.4 R4.2 | length 505.5
  Top Layer w18: R4.2@2332.56,2250 v4(2365,2250)
  Midlayer 2 w18: v4(2365,2250) 2781.78,2250 2814.18,2282.39 v3(2814.18,2292.9)
NetQ2_4: Q2.4 R54.2 | length 752.2
  Top Layer w18: R54.2@2332.56,2195 v4(2365,2195)
  Midlayer 2 w18: v4(2365,2195) 2368.25,2198.25 2803.22,2198.25 2838.02,2233.05 2934.64,2233.05 2994.49,2292.9 v3(3044.18,2292.9)
NetQ7_4: Q7.4 R3.2 | length 499.6
  Top Layer w18: R3.2@2332.56,1160 2337.56,1165 v4(2365,1165)
  Midlayer 2 w18: v4(2365,1165) 2369.13,1160.87 2783.7,1160.87 2814.18,1191.35 v3(2814.18,1192.9)
NetQ8_4: Q8.4 R56.2 | length 748.4
  Top Layer w18: R56.2@2332.56,1105 v4(2365,1105)
  Midlayer 2 w18: v4(2365,1105) 2369.13,1109.13 2900.72,1109.13 2983.42,1191.83 v3(3045,1191.83)
PFM/SYNC1: R15.2 R20.1 TP5.1 U2.17 | length 3331.9
  Top Layer w8: R20.1@2045,2315.31 R15.2@2085,2315.31 ; v4(2065,2315) 2065,2256.52 2084.55,2236.96 2084.55,2220.88 U2.17@2085.47,2219.96
  Midlayer 4 w10: v4(2065,2315) 2150,2315 2188.78,2353.78 2188.78,2380 2020,2548.78 2020,2725 2285,2990 3320,2990 3420,3090 3420,3218.35 3359.35,3279 2629,3279 TP5.1@2550,3200
PFM/SYNC2: R40.2 R43.1 R45.1 TP11.1 U5.17 | length 3431.6
  Top Layer w8: R45.1@2045,1185.32 2045.16,1185.16 v4@2064.84,1185.16 ; v4@2065,1185.31 R40.2@2085,1185.31 ; v4@2066.84,1183.16 2066.84,1158.64 2084.55,1140.93 2084.55,1120.88 U5.17@2085.47,1119.96 ; v4(2155,2355) 2155.16,2355.16 2155.16,2379.84 R43.1@2155.31,2380
  Midlayer 2 w12: v4(2065,1185) 1986.54,1185 1931.22,1129.68 1931.22,733.78 2465,200 TP11.1@2550,200
  Midlayer 4 w8: v4(2065,1185) 2065,1260 2083.18,1278.18 2083.18,1968.85 2053.78,1998.25 2004.3,1998.25 1969.65,2032.91 1850.31,2032.91 1740,2143.22 1740,2299.14 1805.86,2365 1851.22,2365 1890,2326.22 1920,2326.22 2008.78,2415 2129.92,2415 2155,2389.92 v4(2155,2355)
PG/SYNCOUT1: R10.1 R43.2 TP4.1 U2.16 | length 3814.3
  Top Layer w9: v4(2095,2285) 2095.06,2284.94 2095.06,2262.5 2105.08,2252.49 2105.08,2220.04 U2.16@2105.16,2219.96 ; R43.2@2194.69,2380 v4(2220,2380) R10.1@2245.31,2380
  Midlayer 2 w9: v4(2095,2285) 2095,2363.7 2101.37,2370.08 2101.37,2391.35 2106.65,2396.63 2203.37,2396.63 v4(2220,2380)
  Midlayer 4 w9: TP4.1@2150,3200 2246.38,3296.38 3366.54,3296.38 3437.37,3225.55 3437.37,3082.8 3327.2,2972.63 2292.2,2972.63 2045,2725.43 2045,2555 v4(2220,2380)
PG/SYNCOUT2: R35.1 TP10.1 U5.16 | length 1842.2
  Top Layer w9: v4(2100,1155) 2100,1152.56 2105.08,1147.49 2105.08,1120.04 U5.16@2105.16,1119.96 ; v4(2220,1290) R35.1@2245.31,1290
  Midlayer 4 w9: TP10.1@2150,200 1975.6,374.4 1975.6,881.22 2037.25,942.87 2037.25,990.43 2002.47,1025.2 1941.97,1025.2 1914.92,1052.25 1819.52,1052.25 1787.62,1084.14 1787.62,1125.87 1823.13,1161.37 1882.41,1161.37 1910.15,1133.63 2076.19,1133.63 2096.35,1153.78 2100,1153.78 v4(2100,1155) 2101.37,1153.63 2133.85,1153.63 2185,1204.77 2185,1266.47 2207.92,1289.39 2219.39,1289.39 v4(2220,1290)
RT1: R18.1 U2.2 | length 87.6
  Top Layer w9: R18.1@1964.68,2075 1991.02,2075 2006.06,2090.04 U2.2@2046.1,2090.04
RT2: R44.1 U5.2 | length 92.6
  Top Layer w8: R44.1@1959.68,975 1961.65,975 1976.69,990.04 U5.2@2046.1,990.04
SW1: C32.2 C35.1 D2.3 D4.1 L4.1 L5.1 Q1.1 Q1.2 Q1.3 Q2.1 Q2.2 Q2.3 Q4.5-6 Q5.5-6 R11.2 U2.12 | length 2575
  Top Layer w9: U2.12@2183.9,2219.96 2183.9,2226.85 2202.37,2245.33 2202.37,2254.66 2203.58,2255.87 2205.55,2255.87 C32.2@2209.69,2260 v4(2240,2260)
  Top Layer w12: v4(1820,2300) 1821.15,2298.85 1843.59,2298.85 R11.2@1852.44,2290
  Top Layer w30: C35.1@3065,1887.56 3065.98,1887.56 3100.3,1921.88 3100.3,1923.31 3102.74,1925.74 3102.74,2022.13 3126.89,2046.29 3187.05,2046.29 3230.71,2089.95 L4.1@3230.71,2250
  Midlayer 2 w12: v4(1820,2300) 1863.78,2300 1998.78,2435 2260,2435 2374.15,2320.85 2864.15,2320.85 v4(2925,2260)
  Midlayer 2 w18: v4(2240,2260) 2299.34,2260 2335.22,2224.13 2792.5,2224.13 2827.3,2258.93 2923.93,2258.93 v4(2925,2260)
  Bottom Layer w18: D4.1@2239.47,2219 2240,2219.53 v4(2240,2260)
SW2: C74.2 C77.1 D6.3 D8.1 L6.1 L7.1 Q7.1 Q7.2 Q7.3 Q8.1 Q8.2 Q8.3 Q9.5-6 Q10.5-6 R36.2 U5.12 | length 2492
  Top Layer w9: v4(1820,1190) R36.2@1847.44,1190 ; U5.12@2183.9,1119.96 2184.32,1120.38 2184.32,1133.27 2188.35,1137.3 2188.35,1137.45 2194.91,1144 2207.47,1144 2214.69,1151.22 C74.2@2214.69,1165 v4(2240,1165)
  Top Layer w20: L6.1@3189.37,968.9 L7.1@3189.37,1150
  Top Layer w30: C77.1@3065.98,787.98 3100.3,822.3 ; 3102.74,826.17 3102.74,922.55 L7.1@3126.89,946.71
  Midlayer 2 w12: v4(1820,1190) 1990,1360 2240,1360 2375,1225 2860,1225 v4(2920,1165)
  Midlayer 2 w18: v4(2240,1165) 2270,1135 2890,1135 v4(2920,1165)
  Bottom Layer w18: v4(2240,1165) 2247.46,1157.54 2247.46,1123.01 D8.1@2256.47,1114
Vbst1: C32.1 D1.1 U2.13 | length 114.3
  Top Layer w9: U2.13@2164.21,2219.96 2164.21,2254.66 2169.56,2260 C32.1@2170.31,2260 2170.88,2260 2176.22,2265.34 2176.22,2271.81 2196.69,2292.28 D1.1@2196.69,2320
Vbst2: C74.1 D5.1 U5.13 | length 123.8
  Top Layer w9: U5.13@2164.21,1119.96 2164.63,1120.38 2164.63,1137.45 2173.35,1146.16 2173.35,1163.03 C74.1@2175.31,1165 2175.88,1165 2181.22,1170.34 2181.22,1176.81 2196.69,1192.28 D5.1@2196.69,1230
VCC1: C34.1 D1.2 R10.2 U2.7 | length 570.2
  Top Layer w9: U2.7@2144.53,2090.04 2144.53,2062.91 2155,2052.44 v4(2155,2050) 2156.72,2048.28 2165.15,2048.28 2182.44,2030.98 C34.1@2182.44,2030 C34.1@2185,2027.44 ; D1.2@2278.31,2320 D1.2@2279.15,2320.85 ; v4@2279.15,2349.15 2280,2350 v4@2279.84,2350.16 ; R10.2@2279.69,2380 R10.2@2279.84,2379.84 ; D1.2@2284.15,2320.85 v4@2284.15,2349.15 ; v4@2284.84,2350.16 R10.2@2284.84,2379.84
  Midlayer 2 w12: v4(2155,2050) 2155,2100 2185,2130 2185,2185 2160,2210 2160,2310.5 2200,2350.5 2284.5,2350.5 v4(2285,2350)
VCC2: C76.1 D5.2 R35.2 U5.7 | length 488.1
  Top Layer w9: D5.2@2283.31,1225 2284.15,1225.85 2284.15,1254.15 v4(2285,1255) 2284.84,1255.16 R35.2@2285,1290 ; R35.2@2284.69,1290 R35.2@2284.84,1289.84
  Midlayer 2 w12: v4@2155.71,950 v4(2155,950) 2182.77,977.77 2182.77,1088.07 2170,1100.84 2170,1228.76 2196.24,1255 v4(2285,1255)
VCCX1: C48.2 R7.2 U2.15 | length 2534.5
  Top Layer w9: U2.15@2124.84,2219.96 2124.92,2220.04 2124.92,2274.92 v4(2125,2275) C48.2@2125,2300.31 C48.2@2130,2295.31
  Top Layer w12: v4(3770,2700) R7.2@3805.31,2700
  Midlayer 2 w9: v4@2125,2274.92 v4(2125,2275) v4(2125,2275)
  Midlayer 4 w12: v4(2125,2275) v4(2125,2275) 2142.65,2275 2210.53,2342.87 2228.03,2342.87 2235.65,2350.5 2235.84,2350.5 2242.87,2357.53 2242.87,2393.78 2066.73,2569.93 2066.73,2692.73 2249,2875 3595,2875 v4(3770,2700)
VCCX2: C90.2 R31.1 U5.15 | length 2381
  Top Layer w9: U5.15@2124.84,1119.96 2124.92,1120.04 2124.92,1174.92 v4(2125,1175) C90.2@2125,1200.31
  Top Layer w12: v4(3775,1595) R31.1@3805.31,1595
  Midlayer 4 w12: v4(2125,1175) 2157.87,1207.87 2157.87,1327.11 2116.93,1368.05 2116.93,1680 2166.93,1730 3640,1730 v4(3775,1595)
VDDA1: C33.2 R15.1 R19.2 R22.1 U2.6 | length 844.5
  Top Layer w9: v4(2000,1970) R19.2@2000,1995.31 ; v4(2080,2380) 2081.72,2378.28 2081.72,2357.96 R15.1@2085,2354.69 ; U2.6@2124.84,2090.04 2124.92,2089.96 2124.92,2034.76 C33.2@2125,2034.69 2125,2032.72 2130.34,2027.37 2132.09,2027.37 2155,2004.47 R22.1@2155,1969.68 2155.16,1969.84 2179.84,1969.84 v4(2180,1970)
  Midlayer 2 w9: v4(2000,1970) 2000,1993.35 ; v4(2080,2380) 2000,2300 2000,1993.35 ; v4(2180,1970) 2156.65,1993.35 2000,1993.35
VDDA2: C75.2 R40.1 R46.1 R51.1 U5.6 | length 836.4
  Top Layer w8: R40.1@2085,1224.68 2088.09,1227.77 2088.09,1248.09 v4(2090,1250)
  Top Layer w9: v4(2000,870) R46.1@2000,895.32 ; U5.6@2124.84,990.04 U5.6@2124.84,990.04 2124.76,936.18 2124.69,936.1 2124.69,934.13 2130.03,928.79 2131.78,928.79 2155,905.57 R51.1@2155,869.68 2155.16,869.84 2179.84,869.84 v4(2180,870)
  Midlayer 2 w8: v4(2000,870) 2000,893.35 ; v4@2090,1248.76 2090,1180.48 1979.13,1069.61 1979.13,934.13 2000,913.26 2000,893.35 ; v4(2180,870) 2156.65,893.35 2000,893.35
  Midlayer 4 w8: v4@2090,1248.76 2090.45,1249.2 2090,1249.65 v4(2090,1250)
VIN: C1.2 C8.1 C9.1 C10.1 C11.1 C12.2 C13.2 C14.2 C15.2 C16.2 C17.1 C18.1 C19.1 C20.1 C21.2 C22.2 C23.2 C24.2 C25.1 C26.1 C27.1 C28.1 C29.2 C30.1 C54.2 C55.2 C56.2 C57.2 C58.2 C59.1 C60.1 C61.1 C62.1 C63.2 C64.2 C65.2 C66.2 C67.2 C68.1 C69.1 C70.1 C71.1 C72.1 C100.2 C101.2 C102.2 C103.2 J1.1 L1.1 Q1.5-6 Q2.5-6 Q7.5-6 Q8.5-6 R6.2 R29.2 U2.10 U5.10 | length 214.5
  Top Layer w8: R6.2@1995,2332.56 v4(1995,2365) ; U5.10@2199.65,1025.47 2199.88,1025.24 2224.76,1025.24 v4(2225,1025) ; U2.10@2199.65,2125.47 2199.88,2125.24 2224.76,2125.24 v4(2225,2125)
  Top Layer w12: R29.2@1995,1232.56 v4(1995,1260) ; C72.1@2265.47,1005 C72.1@2265.47,1009.35
  Top Layer w15: v4(2225,1025) 2249.82,1025 C72.1@2265.47,1009.35 ; v4(2225,2125) 2251.32,2125 2265.47,2110.85 C30.1@2265.47,2105
  other v1: 2375,1480 2495,1480 2615,1480 2790,1480 2815,1480 2895,1480 2920,1480 3080,1480 3200,1480 3320,1480 2375,1505 2495,1505 2615,1505 2790,1505 2815,1505 2895,1505 2920,1505 3080,1505 3200,1505 3320,1505 2375,1530 2495,1530 2615,1530 3080,1530 3200,1530 3320,1530 2375,1555 2495,1555 2615,1555 3080,1555 3200,1555 3320,1555 1450,1790 1550,1790 1650,1790 1450,1890 1550,1890 1650,1890 1490,1980 1590,1980 1670,1980 1670,2060 1490,2080 1590,2080 1340,2160 1440,2160 1540,2160 1670,2160 1490,2237.35 1590,2237.35 1340,2260 1670,2260 1340,2360 1670,2360 1340,2460 1670,2460 1340,2560 1440,2560 1540,2560 1640,2560 2894,2574 2920,2574 2375,2575 2495,2575 2615,2575 2786,2575 2815,2575 3080,2575 3200,2575 3320,2575 2375,2600 2495,2600 2615,2600 2786,2600 2814,2600 2894,2600 2920,2600 3080,2600 3200,2600 3320,2600 2375,2625 2495,2625 2615,2625 3080,2625 3200,2625 3320,2625 2375,2650 2495,2650 2615,2650 3080,2650 3200,2650 3320,2650
  other v3: 2785,1275 2815,1275 2895,1275 2925,1275 3015,1275 3045,1275 2667.11,1275.92 2697.11,1275.92 2785,1305 2815,1305 2895,1305 2925,1305 3015,1305 3045,1305 2667.11,1305.92 2697.11,1305.92 2785,1335 2815,1335 2895,1335 2925,1335 3015,1335 3045,1335 2667.11,1335.92 2697.11,1335.92 2785,1365 2815,1365 2895,1365 2925,1365 3015,1365 3045,1365 2667.11,1365.92 2697.11,1365.92 2785,1395 2815,1395 2895,1395 2925,1395 3015,1395 3045,1395 2667.11,1395.92 2697.11,1395.92 2785,2375 2815,2375 2895,2375 2925,2375 3015,2375 3045,2375 2667.11,2375.92 2697.11,2375.92 2785,2405 2815,2405 2895,2405 2925,2405 3015,2405 3045,2405 2667.11,2405.92 2697.11,2405.92 2785,2435 2815,2435 2895,2435 2925,2435 3015,2435 3045,2435 2667.11,2435.92 2697.11,2435.92 2785,2465 2815,2465 2895,2465 2925,2465 3015,2465 3045,2465 2667.11,2465.92 2697.11,2465.92 2785,2495 2815,2495 2895,2495 2925,2495 3015,2495 3045,2495 2667.11,2495.92 2697.11,2495.92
